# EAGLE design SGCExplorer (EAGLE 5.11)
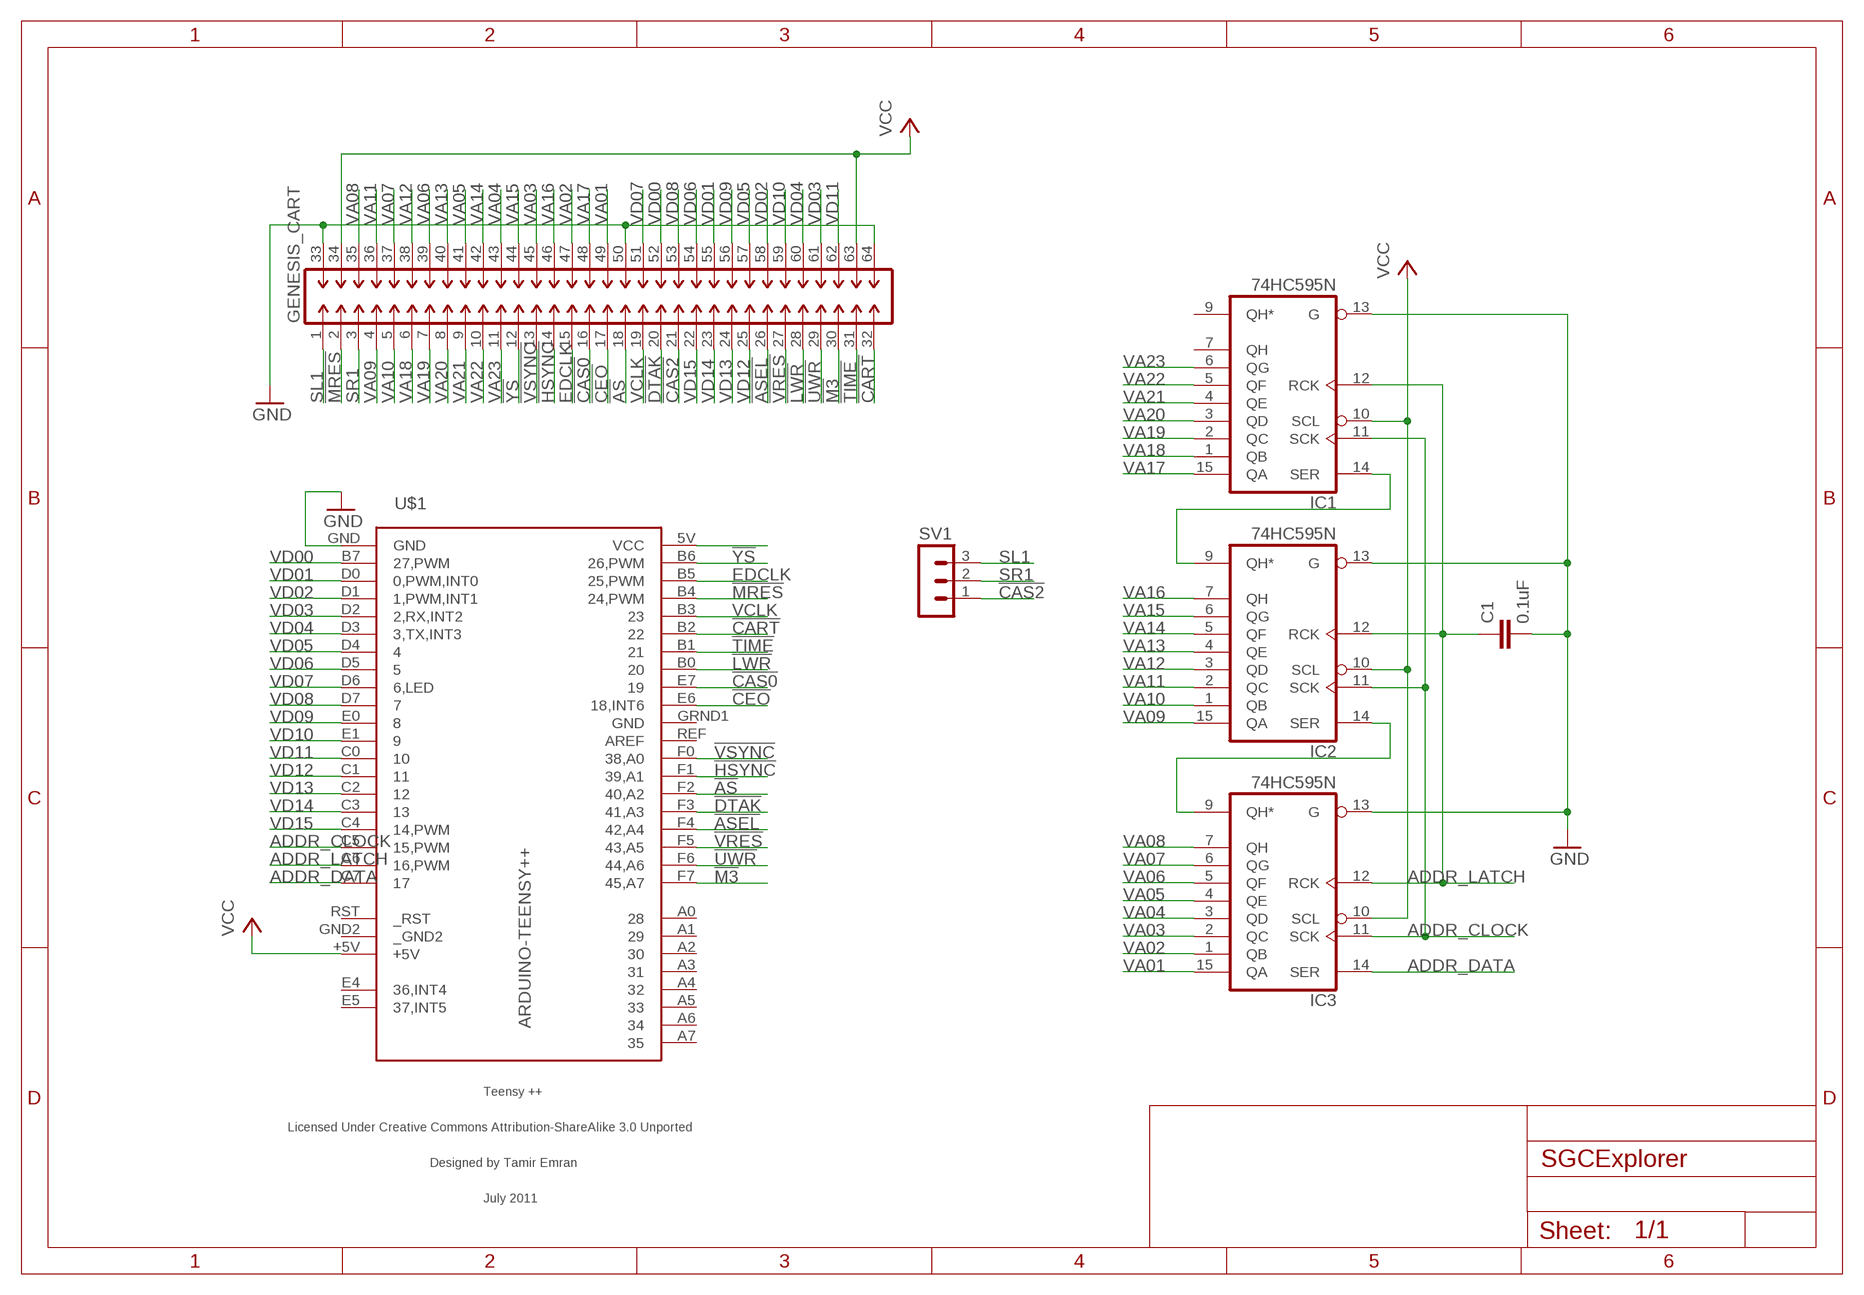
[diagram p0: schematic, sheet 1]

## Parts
C1  0.1uF  C-EU050-024X044  [C050-024X044]
GENESIS_CART  CART_SLOT  [CART_SLOT]
IC1  74HC595N  [DIL16]
IC2  74HC595N  [DIL16]
IC3  74HC595N  [DIL16]
SV1  MA03-1  [MA03-1]
U$1  ARDUINO-TEENSY++  [TEENSY++]

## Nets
!AS: GENESIS_CART.18 U$1.F2(40,A2)
!ASEL: GENESIS_CART.26 U$1.F4(42,A4)
!CART: GENESIS_CART.32 U$1.B2
!CAS0: GENESIS_CART.16 U$1.E7
!CAS2: GENESIS_CART.21 SV1.1
!CEO: GENESIS_CART.17 U$1.E6(18,INT6)
!DTAK: GENESIS_CART.20 U$1.F3(41,A3)
!HSYNC: GENESIS_CART.14 U$1.F1(39,A1)
!LWR: GENESIS_CART.28 U$1.B0
!M3: GENESIS_CART.30 U$1.F7(45,A7)
!MRES: GENESIS_CART.2 U$1.B4(24,PWM)
!TIME: GENESIS_CART.31 U$1.B1
!UWR: GENESIS_CART.29 U$1.F6(44,A6)
!VRES: GENESIS_CART.27 U$1.F5(43,A5)
!VSYNC: GENESIS_CART.13 U$1.F0(38,A0)
!YS: GENESIS_CART.12 U$1.B6(26,PWM)
_UNUSED: U$1.5V(VCC)
ADDR_CLOCK: IC1.11(SCK) IC2.11(SCK) IC3.11(SCK) U$1.C5(15,PWM)
ADDR_DATA: IC3.14(SER) U$1.C7
ADDR_LATCH: C1.1 IC1.12(RCK) IC2.12(RCK) IC3.12(RCK) U$1.C6(16,PWM)
EDCLK: GENESIS_CART.15 U$1.B5(25,PWM)
GND: C1.2 GENESIS_CART.33 GENESIS_CART.50 GENESIS_CART.64 IC1.13(G) IC2.13(G) IC3.13(G) U$1.GND
N$1: IC2.14(SER) IC3.9(QH*)
N$2: IC1.14(SER) IC2.9(QH*)
SL1: GENESIS_CART.1 SV1.3
SR1: GENESIS_CART.3 SV1.2
VA01: GENESIS_CART.49 IC3.15(QA)
VA02: GENESIS_CART.47 IC3.1(QB)
VA03: GENESIS_CART.45 IC3.2(QC)
VA04: GENESIS_CART.43 IC3.3(QD)
VA05: GENESIS_CART.41 IC3.4(QE)
VA06: GENESIS_CART.39 IC3.5(QF)
VA07: GENESIS_CART.37 IC3.6(QG)
VA08: GENESIS_CART.35 IC3.7(QH)
VA09: GENESIS_CART.4 IC2.15(QA)
VA10: GENESIS_CART.5 IC2.1(QB)
VA11: GENESIS_CART.36 IC2.2(QC)
VA12: GENESIS_CART.38 IC2.3(QD)
VA13: GENESIS_CART.40 IC2.4(QE)
VA14: GENESIS_CART.42 IC2.5(QF)
VA15: GENESIS_CART.44 IC2.6(QG)
VA16: GENESIS_CART.46 IC2.7(QH)
VA17: GENESIS_CART.48 IC1.15(QA)
VA18: GENESIS_CART.6 IC1.1(QB)
VA19: GENESIS_CART.7 IC1.2(QC)
VA20: GENESIS_CART.8 IC1.3(QD)
VA21: GENESIS_CART.9 IC1.4(QE)
VA22: GENESIS_CART.10 IC1.5(QF)
VA23: GENESIS_CART.11 IC1.6(QG)
VCC: GENESIS_CART.34 GENESIS_CART.63 IC1.10(SCL) IC2.10(SCL) IC3.10(SCL) U$1.+5V
VCLK: GENESIS_CART.19 U$1.B3
VD00: GENESIS_CART.52 U$1.B7(27,PWM)
VD01: GENESIS_CART.55 U$1.D0(0,PWM,INT0)
VD02: GENESIS_CART.58 U$1.D1(1,PWM,INT1)
VD03: GENESIS_CART.61 U$1.D2(2,RX,INT2)
VD04: GENESIS_CART.60 U$1.D3(3,TX,INT3)
VD05: GENESIS_CART.57 U$1.D4
VD06: GENESIS_CART.54 U$1.D5
VD07: GENESIS_CART.51 U$1.D6(6,LED)
VD08: GENESIS_CART.53 U$1.D7
VD09: GENESIS_CART.56 U$1.E0
VD10: GENESIS_CART.59 U$1.E1
VD11: GENESIS_CART.62 U$1.C0
VD12: GENESIS_CART.25 U$1.C1
VD13: GENESIS_CART.24 U$1.C2
VD14: GENESIS_CART.23 U$1.C3
VD15: GENESIS_CART.22 U$1.C4(14,PWM)
Unconnected: IC1.7(QH) IC1.9(QH*) U$1.A0 U$1.A1 U$1.A2 U$1.A3 U$1.A4 U$1.A5 U$1.A6 U$1.A7 U$1.E4(36,INT4) U$1.E5(37,INT5) U$1.REF(AREF) U$1.RST(_RST)

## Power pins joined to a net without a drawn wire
_GND2: U$1.GND2(_GND2)
GND: IC1.8(GND) IC2.8(GND) IC3.8(GND) U$1.GRND1(GND)
VCC: IC1.16(VCC) IC2.16(VCC) IC3.16(VCC)

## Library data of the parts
C1 = rcl:C-EU: CAPACITOR, European symbol
GENESIS_CART = con-genesis:CART_SLOT: Cartridge Connector
IC1-IC3 = 74xx-eu:74*595: 8-bit SHIFT REGISTER, output latch
SV1 = con-lstb:MA03-1: PIN HEADER; OC_FARNELL: unknown; OC_NEWARK: unknown
U$1 = teensypp:ARDUINO-TEENSY++: Teensy ++ Original Design by Mark Gross Modified Design by Tamir Emran Licensed Under Creative Commons Attribution-ShareAlike 3.0 Unported (CC BY-SA 3.0)

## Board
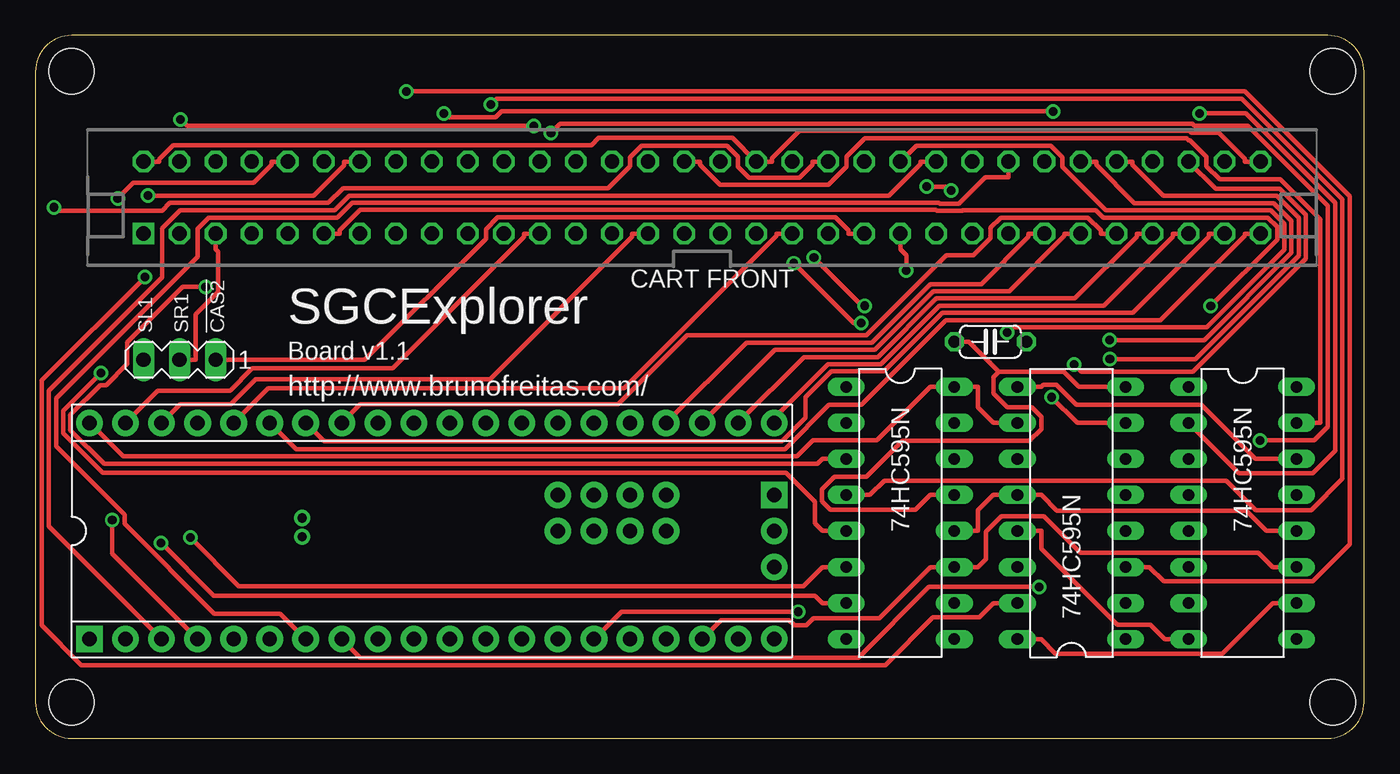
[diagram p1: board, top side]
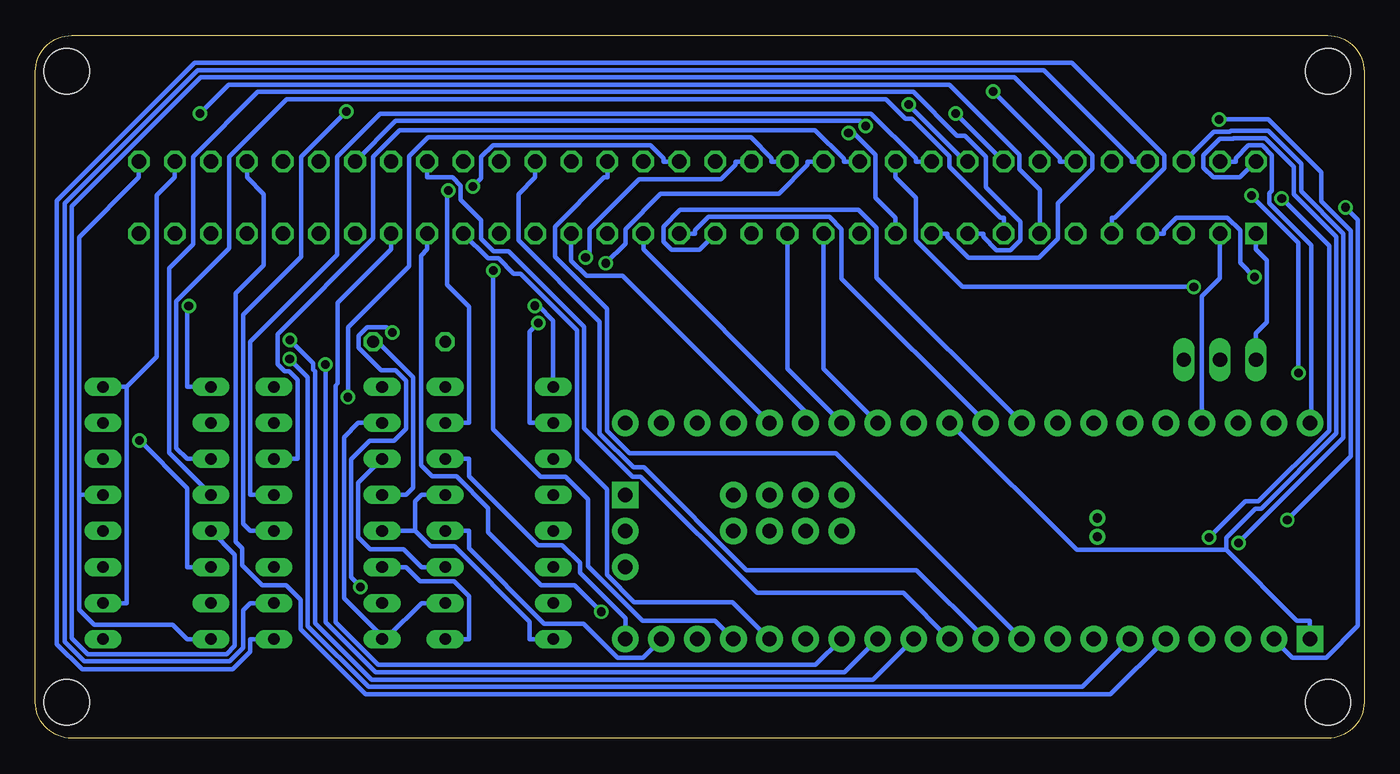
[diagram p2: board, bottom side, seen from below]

Size 93.65 x 49.52 mm. Coordinates in mm from the lower left corner, seen from the top.
Outline: 91.11,0 arc90 93.65,2.54 93.65,46.98 arc90 91.11,49.52 2.54,49.52 arc90 0,46.98 0,2.54 arc90 2.54,0 91.11,0
Copper layers (1*16): Top 0.035mm / dielectric 1.5mm / Bottom 0.035mm
Design rules "ITead_rule": minimum track width 6mil, minimum drill 12mil, track to track 6mil, track to pad 6mil, pad to pad 6mil, via to via 6mil, smd to smd 0mil, copper to edge 10mil, drill to drill 10mil, minimum pad ring 10mil, minimum via ring 6mil, stop-mask expansion 2mil, vias tented up to drill 100mil, thermal gap 10mil
Holes 3.2 mm at 2.54,2.54 91.44,2.54 91.44,46.99 2.54,46.99

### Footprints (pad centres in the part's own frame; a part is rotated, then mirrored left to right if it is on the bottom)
C050-024X044 = drill 0.813 octagon: 1 -2.54,0; 2 2.54,0
CART_SLOT = drill 1.016 square: 1 -39.37,-1.27 | drill 1.016 octagon: 2 -36.83,-1.27; 3 -34.29,-1.27; 4 -31.75,-1.27; 5 -29.21,-1.27; 6 -26.67,-1.27; 7 -24.13,-1.27; 8 -21.59,-1.27; 9 -19.05,-1.27; 10 -16.51,-1.27; 11 -13.97,-1.27; 12 -11.43,-1.27; 13 -8.89,-1.27; 14 -6.35,-1.27; 15 -3.81,-1.27; 16 -1.27,-1.27; 17 1.27,-1.27; 18 3.81,-1.27; 19 6.35,-1.27; 20 8.89,-1.27; 21 11.43,-1.27; 22 13.97,-1.27; 23 16.51,-1.27; 24 19.05,-1.27; 25 21.59,-1.27; 26 24.13,-1.27; 27 26.67,-1.27; 28 29.21,-1.27; 29 31.75,-1.27; 30 34.29,-1.27; 31 36.83,-1.27; 32 39.37,-1.27; 33 -39.37,3.81; 34 -36.83,3.81; 35 -34.29,3.81; 36 -31.75,3.81; 37 -29.21,3.81; 38 -26.67,3.81; 39 -24.13,3.81; 40 -21.59,3.81; 41 -19.05,3.81; 42 -16.51,3.81; 43 -13.97,3.81; 44 -11.43,3.81; 45 -8.89,3.81; 46 -6.35,3.81; 47 -3.81,3.81; 48 -1.27,3.81; 49 1.27,3.81; 50 3.81,3.81; 51 6.35,3.81; 52 8.89,3.81; 53 11.43,3.81; 54 13.97,3.81; 55 16.51,3.81; 56 19.05,3.81; 57 21.59,3.81; 58 24.13,3.81; 59 26.67,3.81; 60 29.21,3.81; 61 31.75,3.81; 62 34.29,3.81; 63 36.83,3.81; 64 39.37,3.81
DIL16 = drill 0.813 long: 1 -8.89,-3.81; 2 -6.35,-3.81; 3 -3.81,-3.81; 4 -1.27,-3.81; 5 1.27,-3.81; 6 3.81,-3.81; 7 6.35,-3.81; 8 8.89,-3.81; 9 8.89,3.81; 10 6.35,3.81; 11 3.81,3.81; 12 1.27,3.81; 13 -1.27,3.81; 14 -3.81,3.81; 15 -6.35,3.81; 16 -8.89,3.81
MA03-1 = drill 1.016 long: 1 -2.54,0; 2 0,0; 3 2.54,0
TEENSY++ = drill 1.016 pad 1.88 round: 5V 24.13,-2.54; +5V -24.13,7.62; A0 8.89,0; A1 11.43,0; A2 13.97,0; A3 16.51,0; A4 8.89,2.54; A5 11.43,2.54; A6 13.97,2.54; A7 16.51,2.54; B0 -6.35,7.62; B1 -8.89,7.62; B2 -11.43,7.62; B3 -13.97,7.62; B4 -16.51,7.62; B5 -19.05,7.62; B6 -21.59,7.62; B7 -21.59,-7.62; C0 6.35,-7.62; C1 8.89,-7.62; C2 11.43,-7.62; C3 13.97,-7.62; C4 16.51,-7.62; C5 19.05,-7.62; C6 21.59,-7.62; C7 24.13,-7.62; D0 -19.05,-7.62; D1 -16.51,-7.62; D2 -13.97,-7.62; D3 -11.43,-7.62; D4 -8.89,-7.62; D5 -6.35,-7.62; D6 -3.81,-7.62; D7 -1.27,-7.62; E0 1.27,-7.62; E1 3.81,-7.62; E6 -1.27,7.62; E7 -3.81,7.62; F0 6.35,7.62; F1 8.89,7.62; F2 11.43,7.62; F3 13.97,7.62; F4 16.51,7.62; F5 19.05,7.62; F6 21.59,7.62; F7 24.13,7.62; GND2 24.13,0; GRND1 1.27,7.62; REF 3.81,7.62 | drill 0.635 pad 1.067 round: E4 -9.144,0.914; E5 -9.144,-0.406 | drill 1.016 pad 1.88 square: GND -24.13,-7.62; RST 24.13,2.54

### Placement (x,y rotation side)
C1  67.31,27.94 180 top
GENESIS_CART  46.99,36.83 0 top
IC1  85.09,15.88 270 top
IC2  73.03,15.88 90 top
IC3  60.96,15.88 270 top
SV1  10.16,26.67 180 top
U$1  27.94,14.61 0 top

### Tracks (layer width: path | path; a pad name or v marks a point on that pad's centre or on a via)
!AS
  Bottom 0.305: GENESIS_CART.18 50.8,34.44 39.37,23.01 U$1.F2
!ASEL
  Top 0.305: U$1.F4 50.1,27.88 58.97,27.88 63.09,32.01 66.68,32.01 70,35.33 70,35.56 GENESIS_CART.26
!CART
  Top 0.305: GENESIS_CART.32 85.24,35.56 85.24,35.4 79.31,29.46 64.17,29.46 58.21,23.5 55.95,23.5 52.82,20.37 18.37,20.37 U$1.B2
!CAS0
  Bottom 0.305: U$1.E7 34.37,32.47 34.37,35.99 35.62,37.24 48.2,37.24 49.38,36.06 49.38,35 48.82,34.43 46.85,34.43 GENESIS_CART.16
!CAS2
  Top 0.305: SV1.1 13.82,26.67 23.21,26.67 31.75,35.21 31.75,35.88 32.57,36.7 56.4,36.7 57.3,35.79 57.3,35.56 GENESIS_CART.21
!CEO
  Bottom 0.305: GENESIS_CART.17 47.14,35.56 47.14,35.79 46.2,36.73 37.69,36.73 36.83,35.87 36.83,32.38 U$1.E6
!DTAK
  Bottom 0.305: U$1.F3 52.26,32.57 54.79,32.57 55.88,33.66 55.88,34.44 GENESIS_CART.20
!HSYNC
  Bottom 0.305: U$1.F1 40.64,26.04 GENESIS_CART.14
!LWR
  Top 0.305: U$1.B0 22.89,23.52 41.06,23.52 45.93,28.39 58.56,28.39 64.22,34.05 | 64.22,34.05 | 64.22,34.05 66.12,34.05 67.31,35.24 67.31,35.96 68.04,36.69 74.18,36.69 75.08,35.79 75.08,35.56 GENESIS_CART.28
!M3
  Top 0.305: U$1.F7 52.07,22.55 55.87,26.36 59.6,26.36 63.72,30.48 75.31,30.48 80.16,35.33 80.16,35.56 GENESIS_CART.30
!MRES
  Bottom 0.305: U$1.B4 11.43,31.15 10.16,32.42 10.16,34.44 GENESIS_CART.2
!TIME
  Top 0.305: U$1.B1 20.35,20.93 52.61,20.93 54.28,22.59 54.28,24.01 56.11,25.85 59.81,25.85 63.93,29.97 77.35,29.97 82.7,35.33 82.7,35.56 GENESIS_CART.31
!UWR
  Top 0.305: U$1.F6 54.17,26.86 59.39,26.86 63.51,30.99 73.28,30.99 77.62,35.33 77.62,35.56 GENESIS_CART.29
!VRES
  Top 0.305: U$1.F5 52.14,27.37 59.18,27.37 63.3,31.5 68.65,31.5 72.54,35.39 72.54,35.56 GENESIS_CART.27
!VSYNC
  Bottom 0.305: U$1.F0 38.1,26.04 GENESIS_CART.13
!YS
  Top 0.305: U$1.B6 8.61,24.48 13.71,24.48 15.29,26.06 25.17,26.06 34.44,35.33 34.44,35.56 GENESIS_CART.12
ADDR_CLOCK
  Top 0.305: U$1.C5 48.34,8.33 53.13,8.33 53.49,7.97 54.36,7.97 54.84,8.45 59.48,8.45 63.09,12.06 IC3.11 66.45,12.06 66.99,12.61 66.99,14.55 68.09,15.66 71.07,15.66 73.64,13.08 86.21,13.08 87.22,12.06 IC1.11
  Bottom 0.305: IC3.11 66.45,12.06 67.72,13.34 70.06,13.34 70.89,14.17 70.89,18.01 IC2.11
ADDR_DATA
  Bottom 0.305: U$1.C7 52.07,8.44 55.28,11.65 55.28,12.35 56.52,13.59 58.23,13.59 63.09,18.45 63.09,19.68 IC3.14
ADDR_LATCH
  Top 0.305: IC3.12 66.45,14.61 66.45,16.05 67.54,17.14 IC2.12 70.89,17.14 72.01,16.03 85.36,16.03 86.78,14.61 87.22,14.61 IC1.12
  Bottom 0.305: IC3.12 63.09,14.61 63.09,13.37 57.8,8.07 55,8.07 52.6,5.67 50.84,5.67 U$1.C6 | IC2.12 67.54,17.14 67.02,17.66 67.02,25.43 69.53,27.94 C1.1
EDCLK
  Top 0.305: U$1.B5 10.19,23.52 13.75,23.52 15.53,25.3 32.03,25.3 42.06,35.33 42.06,35.56 GENESIS_CART.15
GND
  Top 0.305: 67.91,25.82 72.5,25.82 73.56,24.77 75.16,24.77 IC2.8 | 67.91,25.82 65.79,27.94 C1.2 | 67.91,25.82 67.52,25.43 67.52,24.32 68.52,23.32 70.22,23.32 70.89,22.65 70.89,21.79 70.06,20.95 61.11,20.95 58.57,18.41 56.32,18.41 55.44,17.54 55.44,16.7 56.05,16.09 62.03,16.09 63.09,17.14 IC3.13 | GENESIS_CART.33 8.74,40.64 8.74,40.81 9.71,41.78 39.19,41.78 39.71,42.31 49.13,42.31 GENESIS_CART.50 51.92,40.64 51.92,40.87 53.84,42.79 81.35,42.79 81.49,42.66 83.43,42.66 85.24,40.84 85.24,40.64 GENESIS_CART.64 | IC2.13 70.89,14.61 70.89,13.37 76.26,8 78.59,8 79.6,6.99 IC1.8
  Bottom 0.305: GENESIS_CART.33 8.75,39.51 10.64,39.51 11.32,40.2 11.32,41.08 10.16,42.24 9.24,42.24 9.18,42.3 6.97,42.3 4.94,40.26 4.94,38.32 1.96,35.34 1.96,21.48 7.25,16.18 7.66,16.18 9.71,14.12 9.71,13.27 | 9.71,13.27 4.73,8.28 3.81,8.28 U$1.GND | U$1.GRND1 20.25,13.27 9.71,13.27 | 90.58,17.14 90.58,35.31 86.36,39.52 GENESIS_CART.64 | 66.9,14.61 66.9,16.69 66.45,17.14 IC3.13 | 66.9,14.61 65.81,13.52 64.12,13.52 58.83,8.22 58.83,6.99 IC3.8 | 66.9,14.61 68.38,14.61 IC2.13 | IC1.8 82.96,6.99 83.97,8 89.51,8 90.58,9.07 90.58,17.14 | 90.58,17.14 IC1.13
N$1
  Bottom 0.305: IC2.14 67.54,12.06 66.52,11.05 64.14,11.05 63.09,10 63.09,6.99 IC3.9
N$2
  Top 0.305: 73.38,23.5 82.19,23.5 86,19.68 87.22,19.68 IC1.14 | 73.38,23.5 | 73.38,23.5 71.96,24.92 71.04,24.92 70.89,24.77 IC2.9
SL1
  Bottom 0.305: GENESIS_CART.1 7.62,34.44 6.86,33.68 6.86,29.31 7.62,28.55 SV1.3
SR1
  Top 0.305: SV1.2 11.28,26.67 11.28,29.86 12.86,31.45 12.86,34.28 12.7,34.44 GENESIS_CART.3
VA01  (via drill 0.61 pad 1.02)
  Top 0.305: v62.81,38.87 64.26,38.87 v64.54,38.59
  Bottom 0.305: v64.54,38.59 64.63,38.5 64.63,31.95 63.09,30.42 63.09,22.23 IC3.15 | v62.81,38.87 62.23,39.46 62.23,40.96 61.41,41.78 50.29,41.78 49.38,40.87 49.38,40.64 GENESIS_CART.49
VA02  (via drill 0.61 pad 1.02)
  Top 0.305: v54.87,33.87 58.27,30.47 v58.44,30.47
  Bottom 0.305: IC3.1 57.15,29.43 58.19,30.47 v58.44,30.47 | GENESIS_CART.47 44.3,40.64 44.3,40.41 45.31,39.4 51.1,39.4 54.61,35.89 54.61,34.13 v54.87,33.87
VA03  (via drill 0.61 pad 1.02)
  Top 0.305: v53.46,33.47 57.68,29.25 v58.21,29.25
  Bottom 0.305: v58.21,29.25 58.83,28.63 58.83,22.23 IC3.2 | v53.46,33.47 52.07,34.86 52.07,35.88 49.57,38.38 41.25,38.38 39.22,40.41 39.22,40.64 GENESIS_CART.45
VA04  (via drill 0.61 pad 1.02)
  Top 0.305: v12,31.8 10.39,31.8 6.48,27.89 6.48,26.37 4.98,24.88 4.55,24.88 2.47,22.79 2.47,21.71 4.84,19.33 55.12,19.33 55.47,19.68 IC3.3
  Bottom 0.305: GENESIS_CART.43 33.02,39.52 31.6,38.1 31.6,35.1 28.3,31.8 v12,31.8
VA05  (via drill 0.61 pad 1.02)
  Top 0.305: v32.11,44.65 32.52,45.06 85.05,45.06 92.13,37.98 92.13,18.27 89.93,16.07 86.03,16.07 83.94,18.16 59.84,18.16 58.83,17.14 IC3.4
  Bottom 0.305: GENESIS_CART.41 28.09,40.64 v32.11,44.65
VA06  (via drill 0.61 pad 1.02)
  Top 0.305: v4.63,25.74 1.96,23.07 1.96,21.5 4.75,18.71 52.9,18.71 54.94,16.68 54.94,15.14 55.47,14.61 IC3.5 | GENESIS_CART.39 21.74,40.64 21.74,40.37 19.61,38.24 v7.94,38.24
  Bottom 0.305: v7.94,38.24 4.63,34.93 v4.63,25.74
VA07  (via drill 0.61 pad 1.02)
  Top 0.305: v10.93,14.14 14.34,10.72 54.13,10.72 55.47,12.06 IC3.6 | GENESIS_CART.37 16.66,40.64 16.66,40.41 15.39,39.13 6.89,39.13 v5.8,38.04
  Bottom 0.305: v5.8,38.04 2.46,34.7 2.46,21.68 7.46,16.69 8.38,16.69 v10.93,14.14
VA08  (via drill 0.61 pad 1.02)
  Top 0.305: v8.85,13.77 12.57,10.04 54.95,10.04 55.47,9.53 IC3.7
  Bottom 0.305: GENESIS_CART.35 10.59,42.75 9.45,42.75 9.38,42.81 6.75,42.81 4.43,40.49 4.43,38.53 1.45,35.55 1.45,21.17 v8.85,13.77
VA09  (via drill 0.61 pad 1.02)
  Top 0.305: IC2.15 67.54,9.53 66.52,8.51 63.27,8.51 59.92,5.16 3.24,5.16 0.43,7.96 0.43,25.21 v7.72,32.49
  Bottom 0.305: GENESIS_CART.4 14.12,35.56 14.12,35.79 13.24,36.68 9.63,36.68 8.74,35.79 8.74,33.51 v7.72,32.49
VA10
  Bottom 0.305: GENESIS_CART.5 17.78,36.68 17.55,36.68 14.08,40.15 14.08,41.08 20.59,47.59 82.43,47.59 92.14,37.88 92.14,6.62 90.37,4.85 79.74,4.85 78.51,6.08 78.51,6.99 IC2.1
VA11
  Bottom 0.305: GENESIS_CART.36 16.36,40.64 16.36,40.87 22.56,47.07 82.23,47.07 91.59,37.71 91.59,6.79 90.22,5.42 79.98,5.42 79.02,6.37 79.02,9.02 78.51,9.53 IC2.2
VA12  (via drill 0.61 pad 1.02)
  Top 0.305: v26.15,45.58 85.25,45.58 92.66,38.17 92.66,13.67 90.04,11.05 79.53,11.05 78.51,12.06 IC2.3
  Bottom 0.305: v26.15,45.58 21.44,40.87 21.44,40.64 GENESIS_CART.38
VA13  (via drill 0.61 pad 1.02)
  Top 0.305: v71.72,44.17 32.84,44.17 32.45,43.77 29.01,43.77 v28.77,44.01
  Bottom 0.305: GENESIS_CART.40 v28.77,44.01 | v71.72,44.17 74.93,40.96 74.93,33.93 79.02,29.84 79.02,15.11 78.51,14.61 IC2.4
VA14
  Bottom 0.305: GENESIS_CART.42 31.6,40.64 31.6,40.87 34.75,44.02 69.34,44.02 72.39,40.97 72.39,34.07 78.51,27.95 78.51,17.14 IC2.5
VA15
  Bottom 0.305: GENESIS_CART.44 36.68,40.64 36.68,40.83 38.69,42.84 67.98,42.84 69.85,40.98 69.85,35.23 76.6,28.48 76.6,26.36 76.09,25.86 75.77,25.86 75.16,25.25 75.16,19.68 IC2.6
VA16  (via drill 0.61 pad 1.02)
  Top 0.305: IC2.7 73.43,22.23 v71.62,24.03
  Bottom 0.305: v71.62,24.03 71.62,28.95 67.31,33.26 67.31,41.01 65.99,42.34 43.22,42.34 41.76,40.87 41.76,40.64 GENESIS_CART.46
VA17
  Top 0.305: GENESIS_CART.48 46.84,40.64 46.84,40.41 48.25,39 55.89,39 57.15,40.26 57.15,40.96 58.48,42.29 81.14,42.29 81.28,42.15 81.36,42.15 82.55,40.96 82.55,40.32 83.48,39.39 87.76,39.39 90.58,36.58 90.58,22.23 IC1.15
VA18  (via drill 0.61 pad 1.02)
  Top 0.305: GENESIS_CART.6 21.44,35.56 21.44,35.79 22.87,37.22 63.48,37.22 63.55,37.15 65.31,37.15 65.37,37.21 74.73,37.21 75.27,36.68 86.88,36.68 87.52,36.04 87.52,35.14 v82.84,30.46
  Bottom 0.305: IC1.1 82.96,24.77 82.96,30.35 v82.84,30.46
VA19  (via drill 0.61 pad 1.02)
  Top 0.305: IC1.2 84.84,18.67 90.02,18.67 91.61,20.25 91.61,37.72 85.3,44.03 v82.06,44.03
  Bottom 0.305: GENESIS_CART.7 22.86,38.67 24.28,40.09 24.28,41.1 29.23,46.05 80.03,46.05 v82.06,44.03
VA20
  Bottom 0.305: GENESIS_CART.8 25.4,36.68 25.63,36.68 29.21,40.26 29.21,40.99 31.87,43.65 32.33,43.65 33.7,45.03 75.94,45.03 80.01,40.96 80.01,34.52 83.72,30.81 83.72,20.45 82.96,19.68 IC1.3
VA21
  Bottom 0.305: IC1.4 84.24,20.1 84.24,33.11 82.55,34.79 82.55,40.96 77.97,45.54 31.77,45.54 28.7,42.47 28.15,42.47 26.67,40.99 26.67,38.84 24.22,36.39 24.22,35.1 24.92,34.4 25.9,34.4 26.82,35.33 26.82,35.56 GENESIS_CART.9
VA22
  Bottom 0.305: IC1.5 79.6,12.93 79.6,6.51 80.18,5.93 89.98,5.93 91.08,7.04 91.08,37.5 82.02,46.56 24.65,46.56 19.16,41.07 19.16,40.12 21.59,37.69 21.59,35.19 22.92,33.87 27.9,33.87 29.36,35.33 29.36,35.56 GENESIS_CART.10
VA23  (via drill 0.61 pad 1.02)
  Top 0.305: v36.34,42.65 36.99,43.3 81.56,43.3 81.7,43.17 85.44,43.17 91.1,37.51 91.1,21.96 90.13,20.99 v86.32,20.99
  Bottom 0.305: v36.34,42.65 35.99,42.65 34.44,41.1 34.44,38.1 33.02,36.68 GENESIS_CART.11 | v86.32,20.99 82.96,17.62 82.96,12.06 IC1.6
VCC
  Top 0.305: U$1.+5V 6.17,19.86 53.7,19.86 54.82,20.99 59.31,20.99 63.09,24.77 IC3.16 66.45,24.77 66.45,23.32 67.54,22.23 IC2.10 | IC1.10 87.22,9.53 83.67,5.97 71.91,5.97 70.89,6.99 IC2.16
  Bottom 0.305: U$1.+5V 3.71,22.32 3.71,34.73 6.67,37.68 6.67,38.4 6.49,38.57 6.49,41.1 7.16,41.77 8.14,41.77 9.04,40.87 9.04,40.64 GENESIS_CART.34 | GENESIS_CART.63 83.82,39.52 85.09,38.25 85.09,26.9 87.22,24.77 | 87.22,24.77 | 87.22,24.77 IC1.16 | IC1.10 87.22,9.53 87.22,24.77 | 69.22,7.19 71.91,9.88 71.91,21.21 70.89,22.23 IC2.10 | 69.22,7.19 68.79,7.19 66.45,9.53 IC3.10 | 69.22,7.19 IC2.16
VCLK
  Top 0.305: U$1.B3 16.41,24.66 41.48,24.66 52.22,35.4 52.22,35.56 GENESIS_CART.19
VD00  (via drill 0.61 pad 1.02)
  Top 0.305: v1.32,37.41 1.55,37.17 8.93,37.17 9.48,37.72 20.64,37.72 21.67,38.75 40.35,38.75 41.91,40.31 41.91,40.95 42.71,41.76 48.76,41.76 49.53,40.99 49.53,40.26 50.28,39.51 53.86,39.51 54.76,40.41 54.76,40.64 GENESIS_CART.52
  Bottom 0.305: U$1.B7 5.05,5.69 2.66,5.69 0.43,7.92 0.43,36.52 v1.32,37.41
VD01
  Top 0.305: U$1.D0 0.94,14.93 0.94,24.5 | 0.94,24.5 | 0.94,24.5 8.94,32.5 8.94,35.93 10.22,37.21 21.09,37.21 22.12,38.24 60.17,38.24 62.38,40.45 62.38,40.64 GENESIS_CART.55
VD02  (via drill 0.61 pad 1.02)
  Top 0.305: v10.22,43.61 10.68,43.15 v35.12,43.15 | U$1.D1 5.41,13 v5.41,15.39
  Bottom 0.305: GENESIS_CART.58 68.25,43.51 35.48,43.51 v35.12,43.15 | v5.41,15.39 0.94,19.86 0.94,35.76 3.02,37.84 3.02,39.87 6.77,43.61 v10.22,43.61
VD03
  Bottom 0.305: U$1.D2 17.87,3.09 70.37,3.09 74.96,7.68 74.96,9.77 75.98,10.79 77.67,10.79 79.06,12.19 79.06,13.4 79.53,13.86 79.53,31.36 77.55,33.34 77.55,38.33 78.74,39.52 GENESIS_CART.61
VD04  (via drill 0.61 pad 1.02)
  Top 0.305: v75.73,26.72 81.77,26.72 89.05,34 89.05,36.67 87.5,38.22 79.51,38.22 77.32,40.41 77.32,40.64 GENESIS_CART.60
  Bottom 0.305: U$1.D3 19.87,3.62 70.18,3.62 74.45,7.89 74.45,25.44 v75.73,26.72
VD05
  Top 0.305: U$1.D4 17.25,8.79 12.61,8.79 6.28,15.12 6.28,15.74 1.45,20.57 1.45,23.96 11.43,33.94 11.43,35.89 12.22,36.68 21.28,36.68 22.33,37.73 63.7,37.73 63.77,37.66 65.1,37.66 66.97,39.52 68.58,39.52 GENESIS_CART.57
VD06  (via drill 0.61 pad 1.02)
  Top 0.305: v68.5,28.59 68.87,28.96 82.56,28.96 88.03,34.42 88.03,36.25 87.07,37.2 75.46,37.2 72.39,40.27 72.39,40.95 71.58,41.76 62.08,41.76 GENESIS_CART.54 | U$1.D5 22.89,5.68 58.01,5.68 62.99,10.67 v70.74,10.67
  Bottom 0.305: v70.74,10.67 71.4,11.33 71.4,19.66 70.11,20.95 68.38,20.95 67.54,21.79 67.54,25.19 68.27,25.92 69.29,25.92 70.89,27.52 70.89,28.36 70.27,28.97 68.89,28.97 v68.5,28.59
VD07
  Bottom 0.305: GENESIS_CART.51 53.34,39.52 53.57,39.52 57.04,36.05 57.04,33.93 53.37,30.26 53.37,21.68 51.77,20.08 37.23,20.08 U$1.D6
VD08
  Bottom 0.305: GENESIS_CART.53 58.42,39.52 59.61,38.33 59.61,35.09 53.87,29.36 53.87,21.46 51.5,19.08 50.77,19.08 43.54,11.85 31.54,11.85 U$1.D7
VD09
  Bottom 0.305: U$1.E0 32.47,10.25 42.79,10.25 | 42.79,10.25 | 42.79,10.25 50.98,18.44 51.58,18.44 54.97,21.83 54.97,28.98 60.3,34.32 61.35,34.32 62.22,35.2 62.22,36.5 63.68,37.96 63.68,38.94 64.26,39.52 66.04,39.52 GENESIS_CART.56
VD10  (via drill 0.61 pad 1.02)
  Top 0.305: v75.7,28.05 82.38,28.05 88.54,34.21 88.54,36.46 87.28,37.71 77.47,37.71 74.78,40.41 74.78,40.64 GENESIS_CART.59
  Bottom 0.305: U$1.E1 34.6,4.13 69.97,4.13 73.94,8.11 73.94,25.85 74.07,25.98 74.07,26.42 v75.7,28.05
VD11  (via drill 0.61 pad 1.02)
  Top 0.305: v73.21,26.34 73.73,25.82 81.58,25.82 89.56,33.8 89.56,36.88 87.7,38.73 83.19,38.73 GENESIS_CART.62
  Bottom 0.305: U$1.C0 36.64,4.64 69.69,4.64 73.21,8.16 v73.21,26.34
VD12
  Bottom 0.305: GENESIS_CART.25 68.58,34.44 72.34,30.68 72.34,25 72.49,24.86 72.49,8.16 69.49,5.16 38.65,5.16 U$1.C1
VD13  (via drill 0.61 pad 1.02)
  Top 0.305: U$1.C2 41.3,8.91 v53.77,8.91
  Bottom 0.305: GENESIS_CART.24 66.04,34.44 66.48,34 66.48,19.23 65.7,18.45 63.98,18.45 61.73,16.2 61.73,14.53 58,10.79 55.65,10.79 v53.77,8.91
VD14
  Bottom 0.305: U$1.C3 44.52,9.6 51.47,9.6 53.37,11.51 53.37,17.56 55.47,19.66 55.47,28.75 59.45,32.73 59.93,32.73 | 59.93,32.73 | 59.93,32.73 61.02,33.82 61.76,33.82 GENESIS_CART.23
VD15  (via drill 0.61 pad 1.02)
  Top 0.305: GENESIS_CART.22 60.96,34.44 61.38,34.02 v61.38,32.95
  Bottom 0.305: U$1.C4 45.75,8.28 50.87,8.28 54.69,12.1 54.69,16.82 56.28,18.41 58.04,18.41 61.38,21.76 v61.38,32.95

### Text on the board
tPlace: CART FRONT | SL1 | SR1 | !CAS2 | SGCExplorer | Board v1.1 | http://www.brunofreitas.com/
